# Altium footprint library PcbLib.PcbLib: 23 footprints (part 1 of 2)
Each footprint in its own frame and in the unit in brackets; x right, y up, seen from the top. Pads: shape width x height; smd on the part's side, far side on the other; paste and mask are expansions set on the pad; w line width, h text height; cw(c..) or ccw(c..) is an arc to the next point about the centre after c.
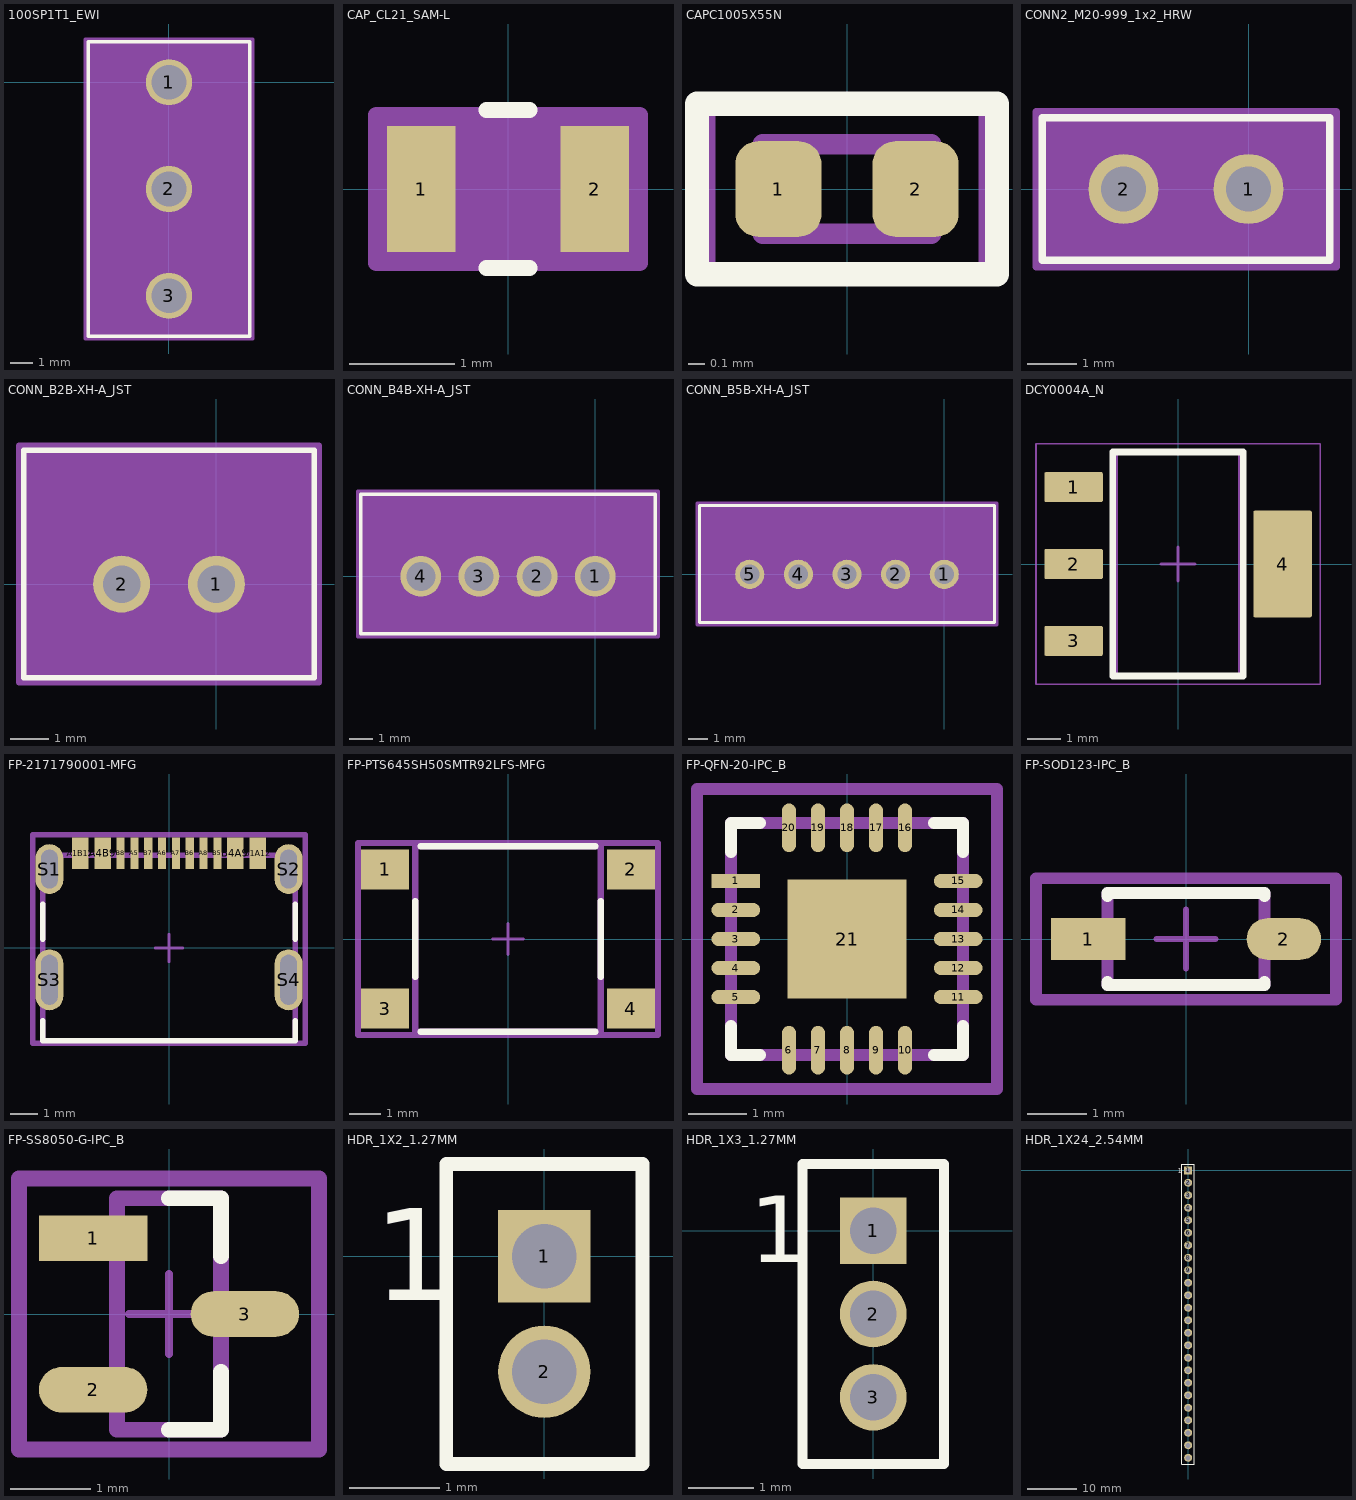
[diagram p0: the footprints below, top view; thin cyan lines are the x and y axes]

## 100SP1T1_EWI [mil]
pads (3):
  round 80 hole 60 paste-99999 mask+0: 1(0,0) 2(0,-185.04) 3(0,-370.08)
Top Overlay:
  lines w6: -140,-440.04 140,-440.04 140,69.96 -140,69.96 -140,-440.04
Top 3D Body:
  circle w20: c0,0 r15
  lines w1: -135,-435.04 135,-435.04 135,64.96 -135,64.96 -135,-435.04
Top Courtyard:
  region: 145,74.96 -145,74.96 -145,-445.04 145,-445.04
  lines w6: -145,-445.04 -145,74.96 145,74.96 145,-445.04 -145,-445.04
3D body "100SP1T1B4M2QE.STEP": height 1168.47, standoff -200.61, extent -135.04,-435.04 135.04,64.96

## CAP_CL21_SAM-L [mm]
pads (2):
  rect 0.65x1.2 smd paste+0 mask+0: 1(-0.825,0) 2(0.825,0)
Top Overlay:
  lines w0.152: -0.204,-0.752 0.204,-0.752 ; -0.204,0.752 0.204,0.752
Top 3D Body:
  circle w0.025: c-0.698,0 r0.076
  lines w0.025: -1,-0.625 -1,0.625 ; -1,-0.625 1,-0.625 ; -1,-0.625 -0.5,-0.625 -0.5,0.625 -1,0.625 ; -1,-0.625 -1,0.625 ; -1,0.625 1,0.625 ; 1,-0.625 1,0.625 ; 1,-0.625 1,0.625 ; 1,-0.625 0.5,-0.625 0.5,0.625 1,0.625
Top Courtyard:
  region: 1.252,-0.702 -1.252,-0.702 -1.252,0.702 1.252,0.702
  lines w0.152: -1.252,-0.702 1.252,-0.702 1.252,0.702 -1.252,0.702 -1.252,-0.702
3D body "CAP_CL21_SAM.step": height 1.35, standoff 0, extent -1,-0.625 1,0.625

## CAPC1005X55N [mm]
pads (2):
  rrect53% 0.54x0.6 smd: 1(-0.43,0) 2(0.43,0)
Top Overlay:
  lines w0.152: -0.94,-0.533 -0.94,0.533 0.94,0.533 0.94,-0.533 -0.94,-0.533
Top 3D Body:
  lines w0.127: -0.53,-0.28 -0.53,0.28 0.53,0.28 0.53,-0.28 -0.53,-0.28
Top Courtyard:
  lines w0.05: -0.85,-0.54 -0.85,0.54 0.85,0.54 0.85,-0.54 -0.85,-0.54
3D body "CL05A105KL5NRNC.STEP": height 0.55, standoff 0, extent -0.5,-0.25 0.5,0.25

## CONN2_M20-999_1x2_HRW [mil]
pads (2):
  round 56 / inner round 60 / far side round 56 hole 36 paste-99999 mask+0: 1(0,0) 2(-100,0)
Top Overlay:
  lines w6: -165,-57 -165,57 65,57 65,-57 -165,-57
Top 3D Body:
  lines w1: -160,-52 -160,52 60,52 60,-52 -160,-52
Top Courtyard:
  region: 70,62 -170,62 -170,-62 70,-62
  lines w6: -170,-62 70,-62 70,62 -170,62 -170,-62
3D body "M20-9990246.STEP": height 222.55, standoff -239.66, extent -150,-50 50,50

## CONN_B2B-XH-A_JST [mil]
pads (2):
  round 59 hole 39 paste-99999 mask+0: 1(0,0) 2(-98.43,0)
Top Overlay:
  lines w6: -199.88,-97.14 -199.88,138.86 101.46,138.86 101.46,-97.14 -199.88,-97.14
Top 3D Body:
  circle w20: c0,0 r15
  lines w1: -194.88,-92.14 -194.88,133.86 96.46,133.86 96.46,-92.14 -194.88,-92.14
Top Courtyard:
  region: 106.46,143.86 -204.88,143.86 -204.88,-102.14 106.46,-102.14
  lines w6: -204.88,-102.14 106.46,-102.14 106.46,143.86 -204.88,143.86 -204.88,-102.14
3D body "B2B-XH-A--3DModel-STEP-56544.STEP": height 275.59, standoff -133.86, extent -195.67,-90.19 95.67,136.19

## CONN_B4B-XH-A_JST [mil]
pads (4):
  round 69 hole 49 paste-99999 mask+0: 1(0,0) 2(-98.43,0) 3(-196.85,0) 4(-295.28,0)
Top Overlay:
  lines w6: -396.64,-97.14 -396.64,138.86 101.36,138.86 101.36,-97.14 -396.64,-97.14
Top 3D Body:
  circle w20: c0,0 r15
  lines w1: -391.64,-92.14 -391.64,133.86 96.36,133.86 96.36,-92.14 -391.64,-92.14
Top Courtyard:
  region: 106.36,143.86 -401.64,143.86 -401.64,-102.14 106.36,-102.14
  lines w6: -401.64,-102.14 106.36,-102.14 106.36,143.86 -401.64,143.86 -401.64,-102.14
3D body "B4B-XH-A.STEP": height 276.09, standoff -133.36, extent -394.09,-91.38 94.09,135

## CONN_B5B-XH-A_JST [mil]
pads (5):
  round 59 hole 39 paste-99999 mask+0: 1(0,0) 2(-98.43,0) 3(-196.85,0) 4(-295.28,0) 5(-393.7,0)
Top Overlay:
  lines w6: -495.35,-97.14 101.65,-97.14 101.65,138.86 -495.35,138.86 -495.35,-97.14
Top 3D Body:
  circle w20: c0,0 r15
  lines w1: -490.35,-92.14 96.65,-92.14 96.65,133.86 -490.35,133.86 -490.35,-92.14
Top Courtyard:
  region: 106.65,143.86 -500.35,143.86 -500.35,-102.14 106.65,-102.14
  lines w6: -500.35,-102.14 -500.35,143.86 106.65,143.86 106.65,-102.14 -500.35,-102.14
3D body "B5B-XH-A.STEP": height 276.09, standoff -133.36, extent -490.61,-92 96,134.38

## DCY0004A_N [mm] "SOT223, 4-Leads, Body 6.7x3.7mm, Pitch 2.3mm, IPC Medium Density"
height 1.8
pads (4):
  rrect11% 1.75x0.9 smd: 1(-3.125,2.3) 2(-3.125,0) 3(-3.125,-2.3)
  rrect6% 1.75x3.2 smd: 4(3.125,0)
Top Overlay:
  lines w0.2: -1.95,-3.35 1.95,-3.35 1.95,3.35 -1.95,3.35 -1.95,-3.35
Top 3D Body:
  lines w0.1: -1.85,-3.35 1.85,-3.35 1.85,3.35 -1.85,3.35 -1.85,-3.35
Top Courtyard:
  lines w0.05: -4.25,-3.6 4.25,-3.6 4.25,3.6 -4.25,3.6 -4.25,-3.6
  lines w0.1: -0.5,0 0.5,0 ; 0,-0.5 0,0.5
3D body "SOT-223.stp": height 1.62, standoff -0.03, extent -3.5,-3.25 3.5,3.25

## FP-2171790001-MFG [mm]
pads (16):
  rect 0.6x1.15 smd paste+0 mask+0: A1B12(-3.2,3.425) A4B9(-2.4,3.425) B1A12(3.2,3.425) B4A9(2.4,3.425)
  rect 0.3x1.15 smd paste+0 mask+0: A5(-1.25,3.425) A6(-0.25,3.425) A7(0.25,3.425) A8(1.25,3.425) B5(1.75,3.425) B6(0.75,3.425) B7(-0.75,3.425) B8(-1.75,3.425)
  rrect100% 1x1.8 hole 1.4 slot 0.6 at 0 deg paste-2539.97 mask+0: S1(-4.32,2.85) S2(4.32,2.85)
  rrect100% 1x2.2 hole 1.8 slot 0.6 at 0 deg paste-2539.97 mask+0: S3(-4.32,-1.15) S4(4.32,-1.15)
Top Overlay:
  lines w0.2: -4.57,-2.625 -4.57,-3.35 4.57,-3.35 4.57,-2.625 ; -4.57,0.325 -4.57,1.575 ; 4.57,0.325 4.57,1.575
Top Assembly:
  lines w0.2: -4.92,-3.45 4.92,-3.45 4.92,4.1 -4.92,4.1 -4.92,-3.45
Top 3D Body:
  lines w0.2: -4.57,-3.35 4.57,-3.35 4.57,3.35 -4.57,3.35 -4.57,-3.35
Top Courtyard:
  lines w0.2: -4.92,-3.45 4.92,-3.45 4.92,4.1 -4.92,4.1 -4.92,-3.45
Top Component Center:
  lines w0.1: -0.5,0 0.5,0 ; 0,-0.5 0,0.5
3D body "Conn_Molex_2171790001_eec.STEP": height 0.25, standoff 0, extent -4.92,-3.45 4.92,4.1

## FP-PTS645SH50SMTR92LFS-MFG [mm]
pads (4):
  rect 1.55x1.3 smd paste+0 mask+0: 1(-3.975,2.25) 2(3.975,2.25) 3(-3.975,-2.25) 4(3.975,-2.25)
Top Overlay:
  lines w0.2: -3,-1.225 -3,1.225 ; -2.825,-3 2.825,-3 ; -2.825,3 2.825,3 ; 3,-1.225 3,1.225
Top Assembly:
  lines w0.2: -4.85,-3.1 4.85,-3.1 4.85,3.1 -4.85,3.1 -4.85,-3.1
Top 3D Body:
  lines w0.2: -3,-3 3,-3 3,3 -3,3 -3,-3
Top Courtyard:
  lines w0.2: -4.85,-3.1 4.85,-3.1 4.85,3.1 -4.85,3.1 -4.85,-3.1
Top Component Center:
  lines w0.1: -0.5,0 0.5,0 ; 0,-0.5 0,0.5
3D body "User Library-PTS645SL43SMTR92-LFS.STEP": height 4.3, standoff 0, extent -4.5,-3 4.5,3

## FP-QFN-20-IPC_B [mm]
pads (21):
  rect 0.84x0.242 smd paste+0 mask+0: 1(-1.916,1)
  rrect100% 0.84x0.242 smd paste+0 mask+0: 2(-1.916,0.5) 3(-1.916,0) 4(-1.916,-0.5) 5(-1.916,-1) 11(1.916,-1) 12(1.916,-0.5) 13(1.916,0) 14(1.916,0.5) 15(1.916,1)
  rrect100% 0.242x0.84 smd paste+0 mask+0: 6(-1,-1.916) 7(-0.5,-1.916) 8(0,-1.916) 9(0.5,-1.916) 10(1,-1.916) 16(1,1.916) 17(0.5,1.916) 18(0,1.916) 19(-0.5,1.916) 20(-1,1.916)
  rect 2.05x2.05 smd paste-1000 mask+0: 21(0,0)
Top Overlay:
  lines w0.2: -2,-1.5 -2,-2 -1.5,-2 ; -2,1.5 -2,2 -1.5,2 ; 1.5,-2 2,-2 2,-1.5 ; 1.5,2 2,2 2,1.5
Top Paste:
  rectangle: -0.648,-0.648 0.648,0.648
Top Assembly:
  lines w0.2: -2.585,-2.585 2.585,-2.585 2.585,2.585 -2.585,2.585 -2.585,-2.585
Top 3D Body:
  lines w0.2: -2,-2 2,-2 2,2 -2,2 -2,-2
Top Courtyard:
  lines w0.2: -2.585,-2.585 2.585,-2.585 2.585,2.585 -2.585,2.585 -2.585,-2.585
Top Component Center:
  lines w0.1: -0.5,0 0.5,0 ; 0,-0.5 0,0.5
3D body "IC_FTDI_FT231XQ-R_eec.STEP": height 0.25, standoff 0, extent -2.585,-2.585 2.585,2.585

## FP-SOD123-IPC_B [mm]
pads (2):
  rect 1.257x0.702 smd paste+0 mask+0: 1(-1.65,0)
  rrect100% 1.257x0.702 smd paste+0 mask+0: 2(1.65,0)
Top Overlay:
  lines w0.2: -1.325,-0.726 -1.325,-0.775 1.325,-0.775 1.325,-0.726 ; -1.325,0.726 -1.325,0.775 1.325,0.775 1.325,0.726
Top Assembly:
  lines w0.2: -2.529,-1.025 -2.529,1.025 2.529,1.025 2.529,-1.025 -2.529,-1.025
Top 3D Body:
  lines w0.2: -1.325,-0.775 -1.325,0.775 1.325,0.775 1.325,-0.775 -1.325,-0.775
Top Courtyard:
  lines w0.2: -2.529,-1.025 -2.529,1.025 2.529,1.025 2.529,-1.025 -2.529,-1.025
Top Component Center:
  lines w0.1: -0.5,0 0.5,0 ; 0,-0.5 0,0.5
3D body "Diode_Diodes_Inc_MMSZ5245B-7-F_eec.STEP": height 0.25, standoff 0, extent -2.529,-1.025 2.529,1.025

## FP-SS8050-G-IPC_B [mm]
pads (3):
  rect 1.357x0.572 smd paste+0 mask+0: 1(-0.951,0.95)
  rrect100% 1.357x0.572 smd paste+0 mask+0: 2(-0.951,-0.95) 3(0.951,0)
Top Overlay:
  lines w0.2: 0,-1.45 0.65,-1.45 0.65,-0.725 ; 0,1.45 0.65,1.45 0.65,0.725
Top Assembly:
  lines w0.2: -1.879,-1.7 1.879,-1.7 1.879,1.7 -1.879,1.7 -1.879,-1.7
Top 3D Body:
  lines w0.2: -0.65,-1.45 0.65,-1.45 0.65,1.45 -0.65,1.45 -0.65,-1.45
Top Courtyard:
  lines w0.2: -1.879,-1.7 1.879,-1.7 1.879,1.7 -1.879,1.7 -1.879,-1.7
Top Component Center:
  lines w0.1: -0.5,0 0.5,0 ; 0,-0.5 0,0.5
3D body "Trans_Comchip_SS8050-G_eec.STEP": height 0.25, standoff 0, extent -1.879,-1.7 1.879,1.7

## HDR_1X2_1.27MM [mil]
pads (2):
  rect 40x40 hole 28: 1(0,0)
  round 40 hole 28: 2(0,-50)
Top Overlay:
  lines w6: -42.5,-90 42.5,-90 42.5,40 -42.5,40 -42.5,-90
  text "1" at -74,-19 h40
3D body "FTS-102-01-F-S.stp": height 154.5, standoff -89.5, extent -42.5,-75 42.5,25

## HDR_1X3_1.27MM [mil]
pads (3):
  rect 40x40 hole 28: 1(0,0)
  round 40 hole 28: 2(0,-50) 3(0,-100)
Top Overlay:
  lines w6: -42.5,-140 -42.5,40 42.5,40 42.5,-140 -42.5,-140
  text "1" at -74,-19 h40
3D body "FTS-103-01-F-S.stp": height 154.5, standoff -89.5, extent -42.5,-125 42.5,25

## HDR_1X24_2.54MM [mil]
pads (24):
  rect 64x64 hole 40: 1(0,0)
  round 64 hole 40: 2(0,-100) 3(0,-200) 4(0,-300) 5(0,-400) 6(0,-500) 7(0,-600) 8(0,-700) 9(0,-800) 10(0,-900) 11(0,-1000) 12(0,-1100) 13(0,-1200) 14(0,-1300) 15(0,-1400) 16(0,-1500) 17(0,-1600) 18(0,-1700) 19(0,-1800) 20(0,-1900) 21(0,-2000) 22(0,-2100) 23(0,-2200) 24(0,-2300)
Top Overlay:
  lines w10: -50,-2350 50,-2350 50,50 -50,50 -50,-2350
  text "1" at -84,-23 h40
3D body "022284245.stp": height 385.5, standoff -119.5, extent -49,-2350 49,50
